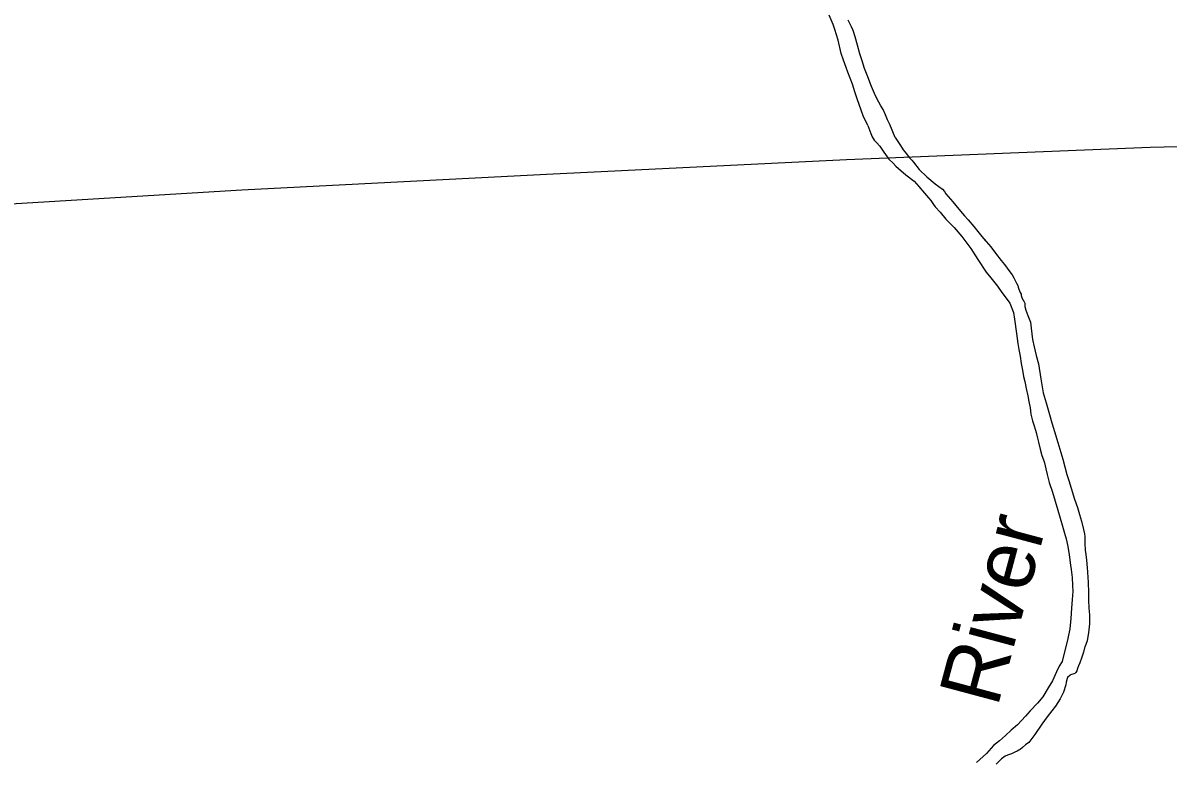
# Model space of a CAD drawing. Extents: x -939622 to -934222, y 1383701 to 1385301.
# Drawn here: x -935735.82 to -935706.1, y 1384246.33 to 1384265.52 of the extents above; entities that cross this region are included whole.
import ezdxf

# ---------------------------------------------------------------- set-up
doc = ezdxf.new("R2010")
doc.units = 0
doc.layers.add('Level 2', color=7, linetype='Continuous')
doc.layers.add('Level 9', color=7, linetype='Continuous')

msp = doc.modelspace()

# ---------------------------------------------------------------- linework, layer by layer
at = {"layer": 'Level 2'}
for points in [[(-935722.236, 1384261.598), (-935714.451, 1384261.979), (-935706.563, 1384262.293), (-935706.2, 1384262.302), (-935698.429, 1384262.444), (-935698.288, 1384262.451), (-935690.292, 1384262.673), (-935690.208, 1384262.685), (-935682.264, 1384263.012), (-935682.15, 1384263.019), (-935672.699, 1384263.196)], [(-935722.236, 1384261.598), (-935714.451, 1384261.979), (-935706.563, 1384262.293), (-935706.2, 1384262.302), (-935698.429, 1384262.444), (-935698.288, 1384262.451), (-935690.292, 1384262.673), (-935690.208, 1384262.685), (-935682.264, 1384263.012), (-935682.15, 1384263.019), (-935674.514, 1384263.162)], [(-935749.617, 1384260.007), (-935745.931, 1384260.207), (-935738.01, 1384260.711), (-935730.139, 1384261.185), (-935722.236, 1384261.598)], [(-935745.931, 1384260.207), (-935738.01, 1384260.711), (-935730.139, 1384261.185), (-935722.236, 1384261.598)]]:
    msp.add_lwpolyline(points, dxfattribs=at)
at = {"layer": 'Level 9'}
for points in [[(-935713.893, 1384262.858), (-935714.019, 1384263.113), (-935714.066, 1384263.253), (-935714.168, 1384263.549), (-935714.229, 1384263.731), (-935714.296, 1384263.928), (-935714.353, 1384264.092), (-935714.416, 1384264.241), (-935714.461, 1384264.366), (-935714.524, 1384264.552), (-935714.588, 1384264.731), (-935714.664, 1384265.075), (-935714.751, 1384265.35), (-935714.792, 1384265.481), (-935714.896, 1384265.723)], [(-935713.187, 1384262.545), (-935713.32, 1384262.881), (-935713.38, 1384263.009), (-935713.433, 1384263.14), (-935713.496, 1384263.271), (-935713.558, 1384263.372), (-935713.613, 1384263.464), (-935713.692, 1384263.631), (-935713.796, 1384263.872), (-935713.893, 1384264.12), (-935713.979, 1384264.341), (-935714.04, 1384264.535), (-935714.104, 1384264.723), (-935714.162, 1384264.947), (-935714.22, 1384265.16), (-935714.272, 1384265.327), (-935714.319, 1384265.419), (-935714.406, 1384265.595)], [(-935713.893, 1384262.858), (-935713.817, 1384262.647), (-935713.781, 1384262.567), (-935713.733, 1384262.482), (-935713.674, 1384262.414), (-935713.587, 1384262.318), (-935713.48, 1384262.165), (-935713.351, 1384261.986), (-935713.239, 1384261.878), (-935713.165, 1384261.805), (-935713.1, 1384261.744), (-935712.908, 1384261.576), (-935712.696, 1384261.412), (-935712.568, 1384261.272), (-935712.428, 1384261.099), (-935712.316, 1384260.982), (-935712.262, 1384260.909), (-935712.228, 1384260.856), (-935712.193, 1384260.803), (-935712.149, 1384260.75), (-935712.021, 1384260.607), (-935711.868, 1384260.422), (-935711.654, 1384260.207), (-935711.458, 1384259.975), (-935711.225, 1384259.661), (-935711.039, 1384259.382), (-935710.821, 1384259.049), (-935710.702, 1384258.905), (-935710.53, 1384258.688), (-935710.42, 1384258.523), (-935710.332, 1384258.412), (-935710.212, 1384258.247), (-935710.117, 1384258.004), (-935710.091, 1384257.833), (-935710.036, 1384257.459), (-935710.003, 1384257.195), (-935709.974, 1384257.043), (-935709.941, 1384256.866), (-935709.917, 1384256.674), (-935709.884, 1384256.504), (-935709.851, 1384256.343), (-935709.823, 1384256.211), (-935709.784, 1384256.026), (-935709.745, 1384255.841), (-935709.713, 1384255.688), (-935709.683, 1384255.527), (-935709.66, 1384255.362), (-935709.621, 1384255.186), (-935709.59, 1384255.084), (-935709.547, 1384254.947), (-935709.527, 1384254.888), (-935709.492, 1384254.742), (-935709.464, 1384254.634), (-935709.422, 1384254.449), (-935709.375, 1384254.291), (-935709.335, 1384254.178), (-935709.311, 1384254.098), (-935709.273, 1384253.939), (-935709.238, 1384253.796), (-935709.217, 1384253.688), (-935709.186, 1384253.584), (-935709.106, 1384253.334), (-935709.029, 1384253.102), (-935708.961, 1384252.866), (-935708.906, 1384252.664), (-935708.845, 1384252.452), (-935708.788, 1384252.27), (-935708.744, 1384252.124), (-935708.702, 1384251.927), (-935708.667, 1384251.706), (-935708.631, 1384251.439), (-935708.616, 1384251.331), (-935708.591, 1384251.121), (-935708.58, 1384250.911), (-935708.578, 1384250.758), (-935708.589, 1384250.55), (-935708.609, 1384250.32), (-935708.626, 1384250.052), (-935708.656, 1384249.786), (-935708.708, 1384249.534), (-935708.85, 1384248.937), (-935708.933, 1384248.814), (-935709, 1384248.67), (-935709.106, 1384248.435), (-935709.211, 1384248.257), (-935709.355, 1384248.02), (-935709.491, 1384247.859), (-935709.685, 1384247.654), (-935709.8, 1384247.515), (-935710.012, 1384247.297), (-935710.172, 1384247.153), (-935710.32, 1384247.016), (-935710.48, 1384246.881), (-935710.629, 1384246.756), (-935710.811, 1384246.551), (-935711.07, 1384246.314)], [(-935713.893, 1384262.858), (-935713.817, 1384262.647), (-935713.781, 1384262.567), (-935713.733, 1384262.482), (-935713.674, 1384262.414), (-935713.587, 1384262.318), (-935713.48, 1384262.165), (-935713.351, 1384261.986), (-935713.239, 1384261.878), (-935713.165, 1384261.805), (-935713.1, 1384261.744), (-935712.908, 1384261.576), (-935712.696, 1384261.412), (-935712.568, 1384261.272), (-935712.428, 1384261.099), (-935712.316, 1384260.982), (-935712.262, 1384260.909), (-935712.228, 1384260.856), (-935712.193, 1384260.803), (-935712.149, 1384260.75), (-935712.021, 1384260.607), (-935711.868, 1384260.422), (-935711.654, 1384260.207), (-935711.458, 1384259.975), (-935711.225, 1384259.661), (-935711.208, 1384259.635)], [(-935713.187, 1384262.545), (-935713.045, 1384262.339), (-935712.975, 1384262.224), (-935712.894, 1384262.121), (-935712.819, 1384262.031), (-935712.753, 1384261.958), (-935712.707, 1384261.905), (-935712.563, 1384261.72), (-935712.361, 1384261.522), (-935712.145, 1384261.343), (-935711.961, 1384261.202), (-935711.908, 1384261.143), (-935711.873, 1384261.081), (-935711.692, 1384260.876), (-935711.608, 1384260.777), (-935711.489, 1384260.633), (-935711.389, 1384260.513), (-935711.292, 1384260.411), (-935711.14, 1384260.233), (-935711.042, 1384260.11), (-935710.933, 1384259.972), (-935710.827, 1384259.846), (-935710.705, 1384259.706), (-935710.58, 1384259.541), (-935710.433, 1384259.357), (-935710.345, 1384259.251), (-935710.276, 1384259.154), (-935710.213, 1384259.06), (-935710.15, 1384258.984), (-935710.109, 1384258.904), (-935710.089, 1384258.865), (-935710.035, 1384258.768), (-935710, 1384258.7), (-935709.989, 1384258.661), (-935709.976, 1384258.61), (-935709.937, 1384258.518), (-935709.917, 1384258.48), (-935709.913, 1384258.444), (-935709.9, 1384258.393), (-935709.868, 1384258.334), (-935709.842, 1384258.293), (-935709.823, 1384258.242), (-935709.818, 1384258.203), (-935709.82, 1384258.155), (-935709.793, 1384258.066), (-935709.74, 1384257.923), (-935709.674, 1384257.754), (-935709.654, 1384257.598), (-935709.623, 1384257.301), (-935709.577, 1384257.107), (-935709.522, 1384256.889), (-935709.461, 1384256.666), (-935709.406, 1384256.279), (-935709.343, 1384255.92), (-935709.262, 1384255.655), (-935709.18, 1384255.354), (-935709.118, 1384255.136), (-935709.048, 1384254.91), (-935708.96, 1384254.63), (-935708.832, 1384254.195), (-935708.78, 1384253.992), (-935708.728, 1384253.792), (-935708.681, 1384253.64), (-935708.615, 1384253.441), (-935708.527, 1384253.155), (-935708.454, 1384252.937), (-935708.403, 1384252.753), (-935708.352, 1384252.58), (-935708.294, 1384252.368), (-935708.269, 1384252.257), (-935708.264, 1384252.185), (-935708.265, 1384252.131), (-935708.266, 1384252.002), (-935708.252, 1384251.834), (-935708.233, 1384251.717), (-935708.216, 1384251.573), (-935708.206, 1384251.375), (-935708.194, 1384251.27), (-935708.183, 1384251.114), (-935708.179, 1384251.009), (-935708.173, 1384250.906), (-935708.17, 1384250.819), (-935708.167, 1384250.75), (-935708.166, 1384250.633), (-935708.166, 1384250.528), (-935708.159, 1384250.323), (-935708.144, 1384250.149), (-935708.145, 1384249.92), (-935708.161, 1384249.76), (-935708.167, 1384249.685), (-935708.196, 1384249.539), (-935708.205, 1384249.479), (-935708.266, 1384249.314), (-935708.274, 1384249.293), (-935708.297, 1384249.178), (-935708.349, 1384249.023), (-935708.393, 1384248.907), (-935708.423, 1384248.828), (-935708.451, 1384248.755), (-935708.47, 1384248.7), (-935708.492, 1384248.651)], [(-935713.187, 1384262.545), (-935713.045, 1384262.339), (-935712.975, 1384262.224), (-935712.894, 1384262.121), (-935712.819, 1384262.031), (-935712.753, 1384261.958), (-935712.707, 1384261.905), (-935712.563, 1384261.72), (-935712.361, 1384261.522), (-935712.145, 1384261.343), (-935711.961, 1384261.202), (-935711.908, 1384261.143), (-935711.873, 1384261.081), (-935711.692, 1384260.876), (-935711.608, 1384260.777), (-935711.489, 1384260.633), (-935711.389, 1384260.513), (-935711.292, 1384260.411), (-935711.14, 1384260.233), (-935711.042, 1384260.11), (-935710.933, 1384259.972), (-935710.842, 1384259.864)], [(-935708.492, 1384248.651), (-935708.524, 1384248.623), (-935708.551, 1384248.619), (-935708.634, 1384248.589), (-935708.652, 1384248.576), (-935708.71, 1384248.526), (-935708.721, 1384248.493), (-935708.745, 1384248.405), (-935708.758, 1384248.335), (-935708.814, 1384248.138), (-935708.907, 1384247.969), (-935709.027, 1384247.781), (-935709.115, 1384247.655), (-935709.239, 1384247.501), (-935709.38, 1384247.312), (-935709.562, 1384247.047), (-935709.72, 1384246.837), (-935709.799, 1384246.778), (-935709.878, 1384246.706), (-935709.939, 1384246.656), (-935709.974, 1384246.636), (-935710.018, 1384246.608), (-935710.077, 1384246.582), (-935710.166, 1384246.543), (-935710.267, 1384246.509), (-935710.326, 1384246.48), (-935710.425, 1384246.411), (-935710.478, 1384246.361), (-935710.565, 1384246.274)]]:
    msp.add_lwpolyline(points, dxfattribs=at)

# ---------------------------------------------------------------- texts
msp.add_text('River', height=1.584, rotation=75, dxfattribs=at).set_placement((-935710.532, 1384247.723))

doc.saveas('drawing.dxf')
